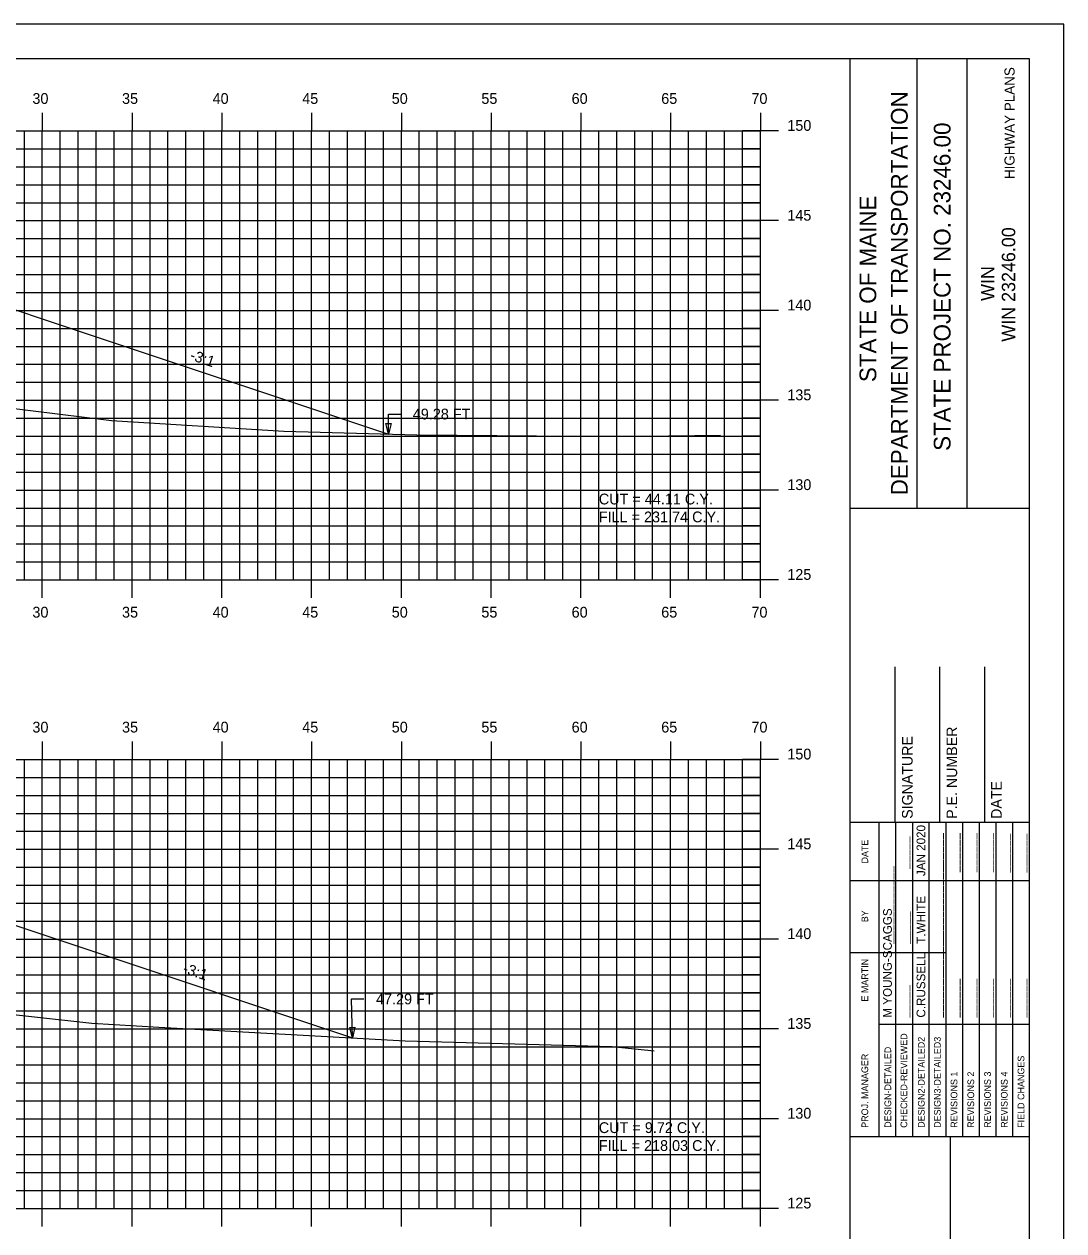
# Model space of a CAD drawing. Extents: x 1144085 to 1144255, y 608981 to 609091.
# Drawn here: x 1144197.3 to 1144255.3, y 609024.1 to 609091.3 of the extents above; entities that cross this region are included whole.
import ezdxf

# ---------------------------------------------------------------- set-up
doc = ezdxf.new("R2010")
doc.units = 0
for name, color, linetype in [('ANNOTATION', 7, 'Continuous'), ('BORDER', 7, 'Continuous'), ('D_Roadway_SlopeLines', 7, 'Continuous'), ('D_Text_Standard', 7, 'Continuous'), ('H_V ANNOTATION', 7, 'Continuous'), ('HIGHWAY_TITLE', 7, 'Continuous'), ('MAJOR', 7, 'Continuous'), ('MINOR', 7, 'Continuous'), ('PLOT BOUNDARY', 7, 'Continuous'), ('S_Roadway_Centerline', 7, 'Continuous')]:
    doc.layers.add(name, color=color, linetype=linetype)

msp = doc.modelspace()

# ---------------------------------------------------------------- linework, layer by layer
for points in [[(1144123.068, 609078.385), (1144153.349, 609078.292), (1144157.349, 609078.452), (1144168.349, 609078.672), (1144179.349, 609078.452), (1144188.751, 609078.076), (1144196.129, 609075.617), (1144199.129, 609074.617), (1144217.63, 609068.45)], [(1144136.907, 609038.164), (1144142.311, 609040.063), (1144145.395, 609041.063), (1144153.348, 609043.642), (1144153.349, 609043.642), (1144157.349, 609043.802), (1144168.349, 609044.022), (1144179.349, 609043.802), (1144190.025, 609043.375), (1144197.322, 609040.943), (1144200.322, 609039.943), (1144215.637, 609034.838)]]:
    msp.add_lwpolyline(points)
at = {"layer": 'BORDER'}
for p, q in [((1144243.349, 608984.335), (1144243.349, 609089.335)), ((1144247.078, 609064.332), (1144247.078, 609089.332)), ((1144249.873, 609064.332), (1144249.873, 609089.332)), ((1144243.35, 609064.329), (1144253.349, 609064.329)), ((1144245.849, 609046.838), (1144245.849, 609055.485)), ((1144248.349, 609046.838), (1144248.349, 609055.485)), ((1144250.849, 609046.838), (1144250.849, 609055.485)), ((1144243.349, 609046.838), (1144253.349, 609046.838)), ((1144243.349, 609029.338), (1144253.349, 609029.338)), ((1144248.94, 608994.338), (1144248.94, 609029.338))]:
    msp.add_line(p, q, dxfattribs=at)
msp.add_lwpolyline([(1144093.349, 608984.335), (1144253.349, 608984.335), (1144253.349, 609089.335), (1144093.349, 609089.335)], close=True, dxfattribs=at)
for points in [[(1144244.964, 609043.588), (1144244.964, 609046.838)], [(1144245.897, 609029.341), (1144245.897, 609046.838)], [(1144246.829, 609046.838), (1144246.829, 609029.341)], [(1144247.76, 609029.341), (1144247.76, 609046.838)], [(1144248.692, 609029.341), (1144248.692, 609046.838)], [(1144249.624, 609029.341), (1144249.624, 609046.838)], [(1144250.555, 609029.341), (1144250.555, 609046.838)], [(1144251.487, 609029.341), (1144251.487, 609046.838)], [(1144252.419, 609029.341), (1144252.419, 609046.838)], [(1144244.965, 609029.341), (1144244.965, 609046.132)], [(1144243.349, 609043.588), (1144253.349, 609043.588)], [(1144243.349, 609039.588), (1144244.965, 609039.588)], [(1144244.964, 609039.588), (1144248.691, 609039.588)], [(1144244.964, 609035.588), (1144253.349, 609035.588)]]:
    msp.add_lwpolyline(points, dxfattribs=at)
at = {"layer": 'D_Roadway_SlopeLines'}
for points in [[(1144196.129, 609075.617), (1144199.129, 609074.617)], [(1144199.129, 609074.617), (1144217.63, 609068.45)], [(1144197.322, 609040.943), (1144200.322, 609039.943)], [(1144200.322, 609039.943), (1144215.637, 609034.838)]]:
    msp.add_lwpolyline(points, dxfattribs=at)
at = {"layer": 'D_Text_Standard'}
for points in [[(1144217.63, 609068.45), (1144217.627, 609069.567), (1144218.307, 609069.567)], [(1144215.637, 609034.838), (1144215.579, 609037.001), (1144216.259, 609037.001)]]:
    msp.add_lwpolyline(points, dxfattribs=at)
for points in [[(1144217.63, 609068.45), (1144217.483, 609069.032), (1144217.774, 609069.032)], [(1144215.637, 609034.838), (1144215.476, 609035.416), (1144215.767, 609035.424)]]:
    msp.add_lwpolyline(points, close=True, dxfattribs=at)
at = {"layer": 'MAJOR'}
for p, q in [((1144198.349, 609086.337), (1144198.349, 609085.335)), ((1144203.349, 609086.337), (1144203.349, 609085.335)), ((1144208.349, 609086.337), (1144208.349, 609085.335)), ((1144213.349, 609086.337), (1144213.349, 609085.335)), ((1144218.349, 609086.337), (1144218.349, 609085.335)), ((1144223.349, 609086.337), (1144223.349, 609085.335)), ((1144228.349, 609086.337), (1144228.349, 609085.335)), ((1144233.349, 609086.337), (1144233.349, 609085.335)), ((1144238.349, 609086.337), (1144238.349, 609085.335)), ((1144098.349, 609085.335), (1144238.349, 609085.335)), ((1144098.349, 609085.335), (1144238.349, 609085.335)), ((1144198.349, 609060.335), (1144198.349, 609085.335)), ((1144203.349, 609060.335), (1144203.349, 609085.335)), ((1144208.349, 609060.335), (1144208.349, 609085.335)), ((1144213.349, 609060.335), (1144213.349, 609085.335)), ((1144218.349, 609060.335), (1144218.349, 609085.335)), ((1144223.349, 609060.335), (1144223.349, 609085.335)), ((1144228.349, 609060.335), (1144228.349, 609085.335)), ((1144233.349, 609060.335), (1144233.349, 609085.335)), ((1144239.351, 609085.335), (1144237.347, 609085.335)), ((1144238.349, 609060.335), (1144238.349, 609085.335)), ((1144238.349, 609060.335), (1144238.349, 609085.335)), ((1144098.349, 609080.335), (1144238.349, 609080.335)), ((1144239.351, 609080.335), (1144237.347, 609080.335)), ((1144098.349, 609075.335), (1144238.349, 609075.335)), ((1144239.351, 609075.335), (1144237.347, 609075.335)), ((1144098.349, 609070.335), (1144238.349, 609070.335)), ((1144239.351, 609070.335), (1144237.347, 609070.335)), ((1144098.349, 609065.335), (1144238.349, 609065.335)), ((1144239.351, 609065.335), (1144237.347, 609065.335)), ((1144098.349, 609060.335), (1144238.349, 609060.335)), ((1144098.349, 609060.335), (1144238.349, 609060.335)), ((1144198.349, 609059.333), (1144198.349, 609060.335)), ((1144203.349, 609059.333), (1144203.349, 609060.335)), ((1144208.349, 609059.333), (1144208.349, 609060.335)), ((1144213.349, 609059.333), (1144213.349, 609060.335)), ((1144218.349, 609059.333), (1144218.349, 609060.335)), ((1144223.349, 609059.333), (1144223.349, 609060.335)), ((1144228.349, 609059.333), (1144228.349, 609060.335)), ((1144233.349, 609059.333), (1144233.349, 609060.335)), ((1144239.351, 609060.335), (1144237.347, 609060.335)), ((1144238.349, 609059.333), (1144238.349, 609060.335)), ((1144198.349, 609051.337), (1144198.349, 609050.335)), ((1144203.349, 609051.337), (1144203.349, 609050.335)), ((1144208.349, 609051.337), (1144208.349, 609050.335)), ((1144213.349, 609051.337), (1144213.349, 609050.335)), ((1144218.349, 609051.337), (1144218.349, 609050.335)), ((1144223.349, 609051.337), (1144223.349, 609050.335)), ((1144228.349, 609051.337), (1144228.349, 609050.335)), ((1144233.349, 609051.337), (1144233.349, 609050.335)), ((1144238.349, 609051.337), (1144238.349, 609050.335)), ((1144098.349, 609050.335), (1144238.349, 609050.335)), ((1144098.349, 609050.335), (1144238.349, 609050.335)), ((1144198.349, 609025.335), (1144198.349, 609050.335)), ((1144203.349, 609025.335), (1144203.349, 609050.335)), ((1144208.349, 609025.335), (1144208.349, 609050.335)), ((1144213.349, 609025.335), (1144213.349, 609050.335)), ((1144218.349, 609025.335), (1144218.349, 609050.335)), ((1144223.349, 609025.335), (1144223.349, 609050.335)), ((1144228.349, 609025.335), (1144228.349, 609050.335)), ((1144233.349, 609025.335), (1144233.349, 609050.335)), ((1144239.351, 609050.335), (1144237.347, 609050.335)), ((1144238.349, 609025.335), (1144238.349, 609050.335)), ((1144238.349, 609025.335), (1144238.349, 609050.335)), ((1144098.349, 609045.335), (1144238.349, 609045.335)), ((1144239.351, 609045.335), (1144237.347, 609045.335)), ((1144098.349, 609040.335), (1144238.349, 609040.335)), ((1144239.351, 609040.335), (1144237.347, 609040.335)), ((1144098.349, 609035.335), (1144238.349, 609035.335)), ((1144239.351, 609035.335), (1144237.347, 609035.335)), ((1144098.349, 609030.335), (1144238.349, 609030.335)), ((1144239.351, 609030.335), (1144237.347, 609030.335)), ((1144098.349, 609025.335), (1144238.349, 609025.335)), ((1144098.349, 609025.335), (1144238.349, 609025.335)), ((1144198.349, 609024.333), (1144198.349, 609025.335)), ((1144203.349, 609024.333), (1144203.349, 609025.335)), ((1144208.349, 609024.333), (1144208.349, 609025.335)), ((1144213.349, 609024.333), (1144213.349, 609025.335)), ((1144218.349, 609024.333), (1144218.349, 609025.335)), ((1144223.349, 609024.333), (1144223.349, 609025.335)), ((1144228.349, 609024.333), (1144228.349, 609025.335)), ((1144233.349, 609024.333), (1144233.349, 609025.335)), ((1144239.351, 609025.335), (1144237.347, 609025.335)), ((1144238.349, 609024.333), (1144238.349, 609025.335))]:
    msp.add_line(p, q, dxfattribs=at)
at = {"layer": 'MINOR'}
for p, q in [((1144197.349, 609060.335), (1144197.349, 609085.335)), ((1144199.349, 609060.335), (1144199.349, 609085.335)), ((1144200.349, 609060.335), (1144200.349, 609085.335)), ((1144201.349, 609060.335), (1144201.349, 609085.335)), ((1144202.349, 609060.335), (1144202.349, 609085.335)), ((1144204.349, 609060.335), (1144204.349, 609085.335)), ((1144205.349, 609060.335), (1144205.349, 609085.335)), ((1144206.349, 609060.335), (1144206.349, 609085.335)), ((1144207.349, 609060.335), (1144207.349, 609085.335)), ((1144209.349, 609060.335), (1144209.349, 609085.335)), ((1144210.349, 609060.335), (1144210.349, 609085.335)), ((1144211.349, 609060.335), (1144211.349, 609085.335)), ((1144212.349, 609060.335), (1144212.349, 609085.335)), ((1144214.349, 609060.335), (1144214.349, 609085.335)), ((1144215.349, 609060.335), (1144215.349, 609085.335)), ((1144216.349, 609060.335), (1144216.349, 609085.335)), ((1144217.349, 609060.335), (1144217.349, 609085.335)), ((1144219.349, 609060.335), (1144219.349, 609085.335)), ((1144220.349, 609060.335), (1144220.349, 609085.335)), ((1144221.349, 609060.335), (1144221.349, 609085.335)), ((1144222.349, 609060.335), (1144222.349, 609085.335)), ((1144224.349, 609060.335), (1144224.349, 609085.335)), ((1144225.349, 609060.335), (1144225.349, 609085.335)), ((1144226.349, 609060.335), (1144226.349, 609085.335)), ((1144227.349, 609060.335), (1144227.349, 609085.335)), ((1144229.349, 609060.335), (1144229.349, 609085.335)), ((1144230.349, 609060.335), (1144230.349, 609085.335)), ((1144231.349, 609060.335), (1144231.349, 609085.335)), ((1144232.349, 609060.335), (1144232.349, 609085.335)), ((1144234.349, 609060.335), (1144234.349, 609085.335)), ((1144235.349, 609060.335), (1144235.349, 609085.335)), ((1144236.349, 609060.335), (1144236.349, 609085.335)), ((1144237.349, 609060.335), (1144237.349, 609085.335)), ((1144098.349, 609084.335), (1144238.349, 609084.335)), ((1144238.349, 609084.335), (1144237.347, 609084.335)), ((1144098.349, 609083.335), (1144238.349, 609083.335)), ((1144238.349, 609083.335), (1144237.347, 609083.335)), ((1144098.349, 609082.335), (1144238.349, 609082.335)), ((1144238.349, 609082.335), (1144237.347, 609082.335)), ((1144098.349, 609081.335), (1144238.349, 609081.335)), ((1144238.349, 609081.335), (1144237.347, 609081.335)), ((1144098.349, 609079.335), (1144238.349, 609079.335)), ((1144238.349, 609079.335), (1144237.347, 609079.335)), ((1144098.349, 609078.335), (1144238.349, 609078.335)), ((1144238.349, 609078.335), (1144237.347, 609078.335)), ((1144098.349, 609077.335), (1144238.349, 609077.335)), ((1144238.349, 609077.335), (1144237.347, 609077.335)), ((1144098.349, 609076.335), (1144238.349, 609076.335)), ((1144238.349, 609076.335), (1144237.347, 609076.335)), ((1144098.349, 609074.335), (1144238.349, 609074.335)), ((1144238.349, 609074.335), (1144237.347, 609074.335)), ((1144098.349, 609073.335), (1144238.349, 609073.335)), ((1144238.349, 609073.335), (1144237.347, 609073.335)), ((1144098.349, 609072.335), (1144238.349, 609072.335)), ((1144238.349, 609072.335), (1144237.347, 609072.335)), ((1144098.349, 609071.335), (1144238.349, 609071.335)), ((1144238.349, 609071.335), (1144237.347, 609071.335)), ((1144098.349, 609069.335), (1144238.349, 609069.335)), ((1144238.349, 609069.335), (1144237.347, 609069.335)), ((1144098.349, 609068.335), (1144238.349, 609068.335)), ((1144238.349, 609068.335), (1144237.347, 609068.335)), ((1144098.349, 609067.335), (1144238.349, 609067.335)), ((1144238.349, 609067.335), (1144237.347, 609067.335)), ((1144098.349, 609066.335), (1144238.349, 609066.335)), ((1144238.349, 609066.335), (1144237.347, 609066.335)), ((1144098.349, 609064.335), (1144238.349, 609064.335)), ((1144238.349, 609064.335), (1144237.347, 609064.335)), ((1144098.349, 609063.335), (1144238.349, 609063.335)), ((1144238.349, 609063.335), (1144237.347, 609063.335)), ((1144098.349, 609062.335), (1144238.349, 609062.335)), ((1144238.349, 609062.335), (1144237.347, 609062.335)), ((1144098.349, 609061.335), (1144238.349, 609061.335)), ((1144238.349, 609061.335), (1144237.347, 609061.335)), ((1144197.349, 609025.335), (1144197.349, 609050.335)), ((1144199.349, 609025.335), (1144199.349, 609050.335)), ((1144200.349, 609025.335), (1144200.349, 609050.335)), ((1144201.349, 609025.335), (1144201.349, 609050.335)), ((1144202.349, 609025.335), (1144202.349, 609050.335)), ((1144204.349, 609025.335), (1144204.349, 609050.335)), ((1144205.349, 609025.335), (1144205.349, 609050.335)), ((1144206.349, 609025.335), (1144206.349, 609050.335)), ((1144207.349, 609025.335), (1144207.349, 609050.335)), ((1144209.349, 609025.335), (1144209.349, 609050.335)), ((1144210.349, 609025.335), (1144210.349, 609050.335)), ((1144211.349, 609025.335), (1144211.349, 609050.335)), ((1144212.349, 609025.335), (1144212.349, 609050.335)), ((1144214.349, 609025.335), (1144214.349, 609050.335)), ((1144215.349, 609025.335), (1144215.349, 609050.335)), ((1144216.349, 609025.335), (1144216.349, 609050.335)), ((1144217.349, 609025.335), (1144217.349, 609050.335)), ((1144219.349, 609025.335), (1144219.349, 609050.335)), ((1144220.349, 609025.335), (1144220.349, 609050.335)), ((1144221.349, 609025.335), (1144221.349, 609050.335)), ((1144222.349, 609025.335), (1144222.349, 609050.335)), ((1144224.349, 609025.335), (1144224.349, 609050.335)), ((1144225.349, 609025.335), (1144225.349, 609050.335)), ((1144226.349, 609025.335), (1144226.349, 609050.335)), ((1144227.349, 609025.335), (1144227.349, 609050.335)), ((1144229.349, 609025.335), (1144229.349, 609050.335)), ((1144230.349, 609025.335), (1144230.349, 609050.335)), ((1144231.349, 609025.335), (1144231.349, 609050.335)), ((1144232.349, 609025.335), (1144232.349, 609050.335)), ((1144234.349, 609025.335), (1144234.349, 609050.335)), ((1144235.349, 609025.335), (1144235.349, 609050.335)), ((1144236.349, 609025.335), (1144236.349, 609050.335)), ((1144237.349, 609025.335), (1144237.349, 609050.335)), ((1144098.349, 609049.335), (1144238.349, 609049.335)), ((1144238.349, 609049.335), (1144237.347, 609049.335)), ((1144098.349, 609048.335), (1144238.349, 609048.335)), ((1144238.349, 609048.335), (1144237.347, 609048.335)), ((1144098.349, 609047.335), (1144238.349, 609047.335)), ((1144238.349, 609047.335), (1144237.347, 609047.335)), ((1144098.349, 609046.335), (1144238.349, 609046.335)), ((1144238.349, 609046.335), (1144237.347, 609046.335)), ((1144098.349, 609044.335), (1144238.349, 609044.335)), ((1144238.349, 609044.335), (1144237.347, 609044.335)), ((1144098.349, 609043.335), (1144238.349, 609043.335)), ((1144238.349, 609043.335), (1144237.347, 609043.335)), ((1144098.349, 609042.335), (1144238.349, 609042.335)), ((1144238.349, 609042.335), (1144237.347, 609042.335)), ((1144098.349, 609041.335), (1144238.349, 609041.335)), ((1144238.349, 609041.335), (1144237.347, 609041.335)), ((1144098.349, 609039.335), (1144238.349, 609039.335)), ((1144238.349, 609039.335), (1144237.347, 609039.335)), ((1144098.349, 609038.335), (1144238.349, 609038.335)), ((1144238.349, 609038.335), (1144237.347, 609038.335)), ((1144098.349, 609037.335), (1144238.349, 609037.335)), ((1144238.349, 609037.335), (1144237.347, 609037.335)), ((1144098.349, 609036.335), (1144238.349, 609036.335)), ((1144238.349, 609036.335), (1144237.347, 609036.335)), ((1144098.349, 609034.335), (1144238.349, 609034.335)), ((1144238.349, 609034.335), (1144237.347, 609034.335)), ((1144098.349, 609033.335), (1144238.349, 609033.335)), ((1144238.349, 609033.335), (1144237.347, 609033.335)), ((1144098.349, 609032.335), (1144238.349, 609032.335)), ((1144238.349, 609032.335), (1144237.347, 609032.335)), ((1144098.349, 609031.335), (1144238.349, 609031.335)), ((1144238.349, 609031.335), (1144237.347, 609031.335)), ((1144098.349, 609029.335), (1144238.349, 609029.335)), ((1144238.349, 609029.335), (1144237.347, 609029.335)), ((1144098.349, 609028.335), (1144238.349, 609028.335)), ((1144238.349, 609028.335), (1144237.347, 609028.335)), ((1144098.349, 609027.335), (1144238.349, 609027.335)), ((1144238.349, 609027.335), (1144237.347, 609027.335)), ((1144098.349, 609026.335), (1144238.349, 609026.335)), ((1144238.349, 609026.335), (1144237.347, 609026.335))]:
    msp.add_line(p, q, dxfattribs=at)
at = {"layer": 'PLOT BOUNDARY'}
msp.add_lwpolyline([(1144085.256, 608981.276), (1144255.256, 608981.276), (1144255.256, 609091.276), (1144085.256, 609091.276)], close=True, dxfattribs=at)
at = {"layer": 'S_Roadway_Centerline'}
for points in [[(1144196.187, 609069.952), (1144202.207, 609069.208), (1144211.795, 609068.608), (1144219.204, 609068.407), (1144230.334, 609068.321), (1144236.135, 609068.392)], [(1144194.528, 609036.383), (1144201.114, 609035.654), (1144204.836, 609035.431), (1144218.563, 609034.677), (1144230.095, 609034.36), (1144232.435, 609034.119)]]:
    msp.add_lwpolyline(points, dxfattribs=at)

# ---------------------------------------------------------------- texts
at = {"layer": 'ANNOTATION'}
for p in [(1144206.529, 609072.604), (1144206.129, 609038.461)]:
    msp.add_text('-3:1', height=0.6, rotation=341.56505, dxfattribs=at).set_placement(p)
at = {"layer": 'BORDER'}
for s, height, p in [('DEPARTMENT OF TRANSPORTATION', 0.93176, (1144246.556, 609065.041)), ('STATE PROJECT NO. 23246.00', 0.93176, (1144248.941, 609067.517)), ('STATE OF MAINE', 0.93176, (1144244.805, 609071.347)), ('WIN 23246.00', 0.74527, (1144252.545, 609073.596)), ('WIN', 0.7453, (1144251.386, 609075.865)), ('P.E. NUMBER', 0.59055, (1144249.31, 609047.03)), ('SIGNATURE', 0.5906, (1144246.83, 609047.03)), ('DATE', 0.5906, (1144251.791, 609047.03)), ('JAN 2020', 0.4845, (1144247.536, 609043.843)), ('DATE', 0.3714, (1144244.354, 609044.544)), ('_____', 0.4845, (1144246.567, 609044.243)), ('______', 0.4845, (1144248.43, 609044.063)), ('______', 0.4845, (1144249.362, 609044.065)), ('______', 0.4845, (1144250.294, 609044.067)), ('______', 0.4845, (1144251.225, 609044.067)), ('______', 0.4845, (1144252.157, 609044.036)), ('______', 0.4845, (1144253.089, 609044.036)), ('____________', 0.48455, (1144245.672, 609040.073)), ('____________', 0.48455, (1144248.43, 609040.073)), ('T.WHITE', 0.4845, (1144247.536, 609040.073)), ('BY', 0.3714, (1144244.354, 609041.273)), ('M YOUNG-SCAGGS', 0.48455, (1144245.672, 609035.961)), ('_____', 0.4845, (1144246.604, 609040.073)), ('____________', 0.48455, (1144248.43, 609035.961)), ('E MARTIN', 0.3727, (1144244.354, 609036.855)), ('C.RUSSELL', 0.4845, (1144247.536, 609035.961)), ('_____', 0.4845, (1144246.567, 609035.961)), ('______', 0.4845, (1144249.362, 609035.961)), ('______', 0.4845, (1144250.294, 609035.961)), ('______', 0.4845, (1144251.225, 609035.961)), ('______', 0.4845, (1144252.157, 609035.961)), ('______', 0.4845, (1144253.089, 609035.961)), ('CHECKED-REVIEWED', 0.37275, (1144246.53, 609029.826)), ('DESIGN2-DETAILED2', 0.37275, (1144247.499, 609029.826)), ('DESIGN3-DETAILED3', 0.37275, (1144248.394, 609029.826)), ('DESIGN-DETAILED', 0.37275, (1144245.636, 609029.826)), ('PROJ. MANAGER', 0.37275, (1144244.354, 609029.826)), ('FIELD CHANGES', 0.37275, (1144253.052, 609029.826)), ('REVISIONS 1', 0.37275, (1144249.325, 609029.826)), ('REVISIONS 2', 0.37275, (1144250.257, 609029.826)), ('REVISIONS 3', 0.37275, (1144251.189, 609029.826)), ('REVISIONS 4', 0.37275, (1144252.121, 609029.826))]:
    msp.add_text(s, height=height, rotation=90, dxfattribs=at).set_placement(p)
at = {"layer": 'D_Text_Standard'}
for s, p in [('49.28 FT', (1144218.987, 609069.267)), ('CUT = 44.11 C.Y.', (1144229.349, 609064.535)), ('FILL = 231.74 C.Y.', (1144229.349, 609063.539)), ('47.29 FT', (1144216.939, 609036.701)), ('CUT = 9.72 C.Y.', (1144229.349, 609029.535)), ('FILL = 218.03 C.Y.', (1144229.349, 609028.539))]:
    msp.add_text(s, height=0.6, dxfattribs=at).set_placement(p)
at = {"layer": 'H_V ANNOTATION'}
for s, p in [('30', (1144197.798, 609086.835)), ('35', (1144202.79, 609086.835)), ('40', (1144207.835, 609086.835)), ('45', (1144212.827, 609086.835)), ('50', (1144217.814, 609086.835)), ('55', (1144222.806, 609086.835)), ('60', (1144227.835, 609086.835)), ('65', (1144232.827, 609086.835)), ('70', (1144237.851, 609086.835)), ('150', (1144239.849, 609085.335)), ('145', (1144239.849, 609080.335)), ('140', (1144239.849, 609075.335)), ('135', (1144239.849, 609070.335)), ('130', (1144239.849, 609065.335)), ('125', (1144239.849, 609060.335)), ('30', (1144197.798, 609058.235)), ('35', (1144202.79, 609058.235)), ('40', (1144207.835, 609058.235)), ('45', (1144212.827, 609058.235)), ('50', (1144217.814, 609058.235)), ('55', (1144222.806, 609058.235)), ('60', (1144227.835, 609058.235)), ('65', (1144232.827, 609058.235)), ('70', (1144237.851, 609058.235)), ('30', (1144197.798, 609051.835)), ('35', (1144202.79, 609051.835)), ('40', (1144207.835, 609051.835)), ('45', (1144212.827, 609051.835)), ('50', (1144217.814, 609051.835)), ('55', (1144222.806, 609051.835)), ('60', (1144227.835, 609051.835)), ('65', (1144232.827, 609051.835)), ('70', (1144237.851, 609051.835)), ('150', (1144239.849, 609050.335)), ('145', (1144239.849, 609045.335)), ('140', (1144239.849, 609040.335)), ('135', (1144239.849, 609035.335)), ('130', (1144239.849, 609030.335)), ('125', (1144239.849, 609025.335))]:
    msp.add_text(s, height=0.6, dxfattribs=at).set_placement(p)
at = {"layer": 'HIGHWAY_TITLE'}
msp.add_text('HIGHWAY PLANS', height=0.55901, rotation=90, dxfattribs=at).set_placement((1144252.508, 609082.65))

doc.saveas('drawing.dxf')
